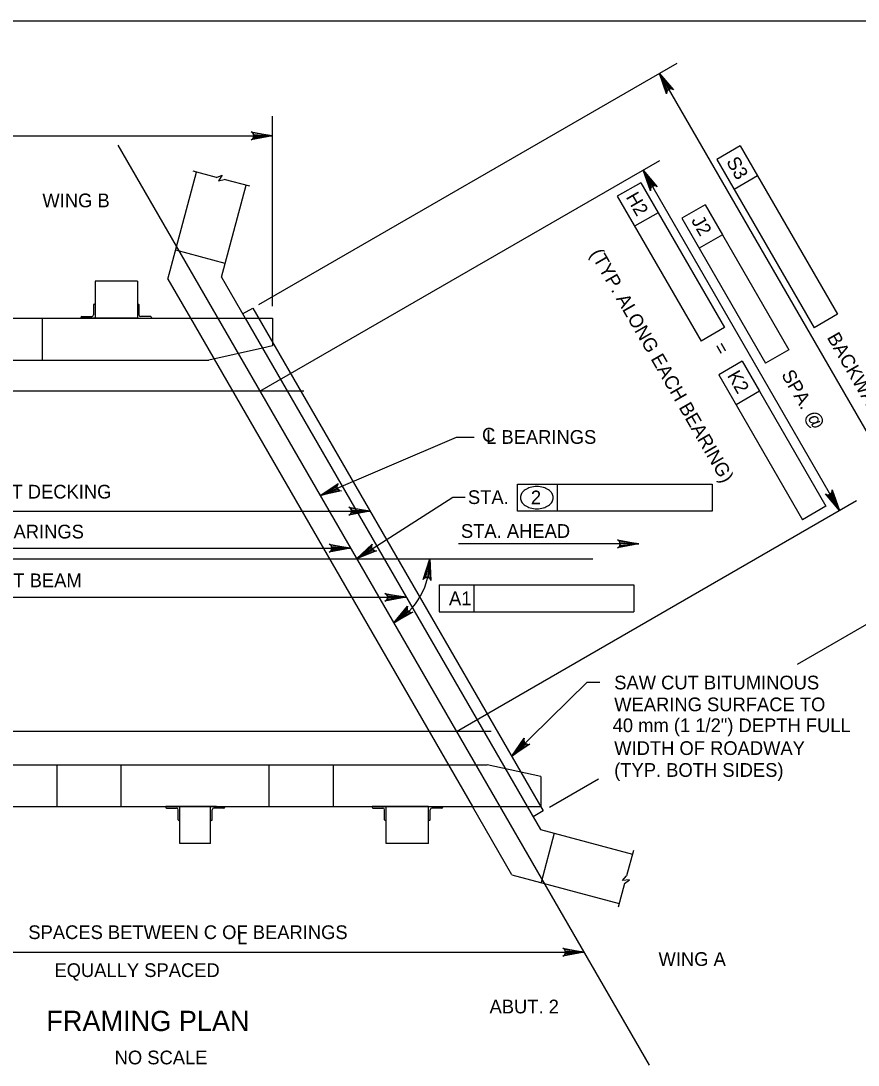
# Model space of a CAD drawing. Extents: x 638263 to 640360, y 293683 to 298655.
# Drawn here: x 638764.4 to 638947.3, y 294034.1 to 294262.5 of the extents above; entities that cross this region are included whole.
import ezdxf

# ---------------------------------------------------------------- set-up
doc = ezdxf.new("R2010")
doc.units = 0
for name, color, linetype in [('2', 7, 'Continuous'), ('3', 7, 'Continuous'), ('4', 7, 'Continuous')]:
    doc.layers.add(name, color=color, linetype=linetype)

msp = doc.modelspace()

# ---------------------------------------------------------------- linework, layer by layer
at = {"layer": '2'}
for p, q in [((638475.46, 294262.46), (639261.46, 294262.46)), ((638796.52, 294205.97), (638802.8, 294229.4)), ((638809.02, 294209.43), (638813.59, 294226.51)), ((638809.02, 294209.43), (638798.22, 294212.32)), ((638808.21, 294206.4), (638809.02, 294209.43)), ((638789.84, 294205.52), (638780.6, 294205.52)), ((638780.6, 294205.52), (638780.6, 294197.43)), ((638789.84, 294205.52), (638789.84, 294197.43)), ((638796.52, 294205.97), (638801.46, 294197.43)), ((638808.21, 294206.4), (638813.39, 294197.43)), ((638780.24, 294200.34), (638780.24, 294198.15)), ((638780.42, 294200.52), (638780.6, 294200.52)), ((638780.6, 294200.52), (638780.6, 294197.43)), ((638790.02, 294200.52), (638789.84, 294200.52)), ((638789.84, 294200.52), (638789.84, 294197.43)), ((638790.2, 294200.34), (638790.2, 294198.15)), ((638777.69, 294197.79), (638779.87, 294197.79)), ((638792.75, 294197.79), (638790.56, 294197.79)), ((638812.84, 294198.38), (638815.08, 294199.67)), ((638815.08, 294199.67), (638878.54, 294089.75)), ((638614.72, 294197.43), (638819.35, 294197.43)), ((638769.05, 294197.43), (638769.05, 294188.31)), ((638777.51, 294197.61), (638777.51, 294197.43)), ((638780.6, 294197.43), (638777.51, 294197.43)), ((638789.84, 294197.43), (638780.6, 294197.43)), ((638789.84, 294197.43), (638792.93, 294197.43)), ((638792.93, 294197.61), (638792.93, 294197.43)), ((638801.46, 294197.43), (638863.07, 294090.7)), ((638813.39, 294197.43), (638875.01, 294090.7)), ((638819.35, 294197.43), (638819.35, 294191.4)), ((638817.17, 294190.91), (638805.49, 294188.31)), ((638819.34, 294191.4), (638817.17, 294190.91)), ((638628.57, 294188.31), (638805.49, 294188.31)), ((638720.51, 294099.82), (638866.31, 294099.82)), ((638772.3, 294090.7), (638772.3, 294099.82)), ((638786.32, 294090.7), (638786.32, 294099.82)), ((638818.66, 294090.7), (638818.66, 294099.82)), ((638832.68, 294090.7), (638832.68, 294099.82)), ((638877.99, 294097.22), (638866.31, 294099.82)), ((638877.99, 294097.22), (638877.99, 294090.7)), ((638673.35, 294090.7), (638877.99, 294090.7)), ((638796.04, 294090.52), (638796.04, 294090.7)), ((638799.13, 294090.7), (638796.04, 294090.7)), ((638796.22, 294090.34), (638798.4, 294090.34)), ((638807.11, 294090.7), (638797.87, 294090.7)), ((638805.85, 294090.7), (638799.13, 294090.7)), ((638799.13, 294087.61), (638799.13, 294090.7)), ((638799.13, 294082.61), (638799.13, 294090.7)), ((638805.85, 294087.61), (638805.85, 294090.7)), ((638805.85, 294090.7), (638808.94, 294090.7)), ((638805.85, 294082.61), (638805.85, 294090.7)), ((638808.76, 294090.34), (638806.58, 294090.34)), ((638808.94, 294090.52), (638808.94, 294090.7)), ((638841.14, 294090.52), (638841.14, 294090.7)), ((638844.24, 294090.7), (638841.14, 294090.7)), ((638841.33, 294090.34), (638843.51, 294090.34)), ((638853.47, 294090.7), (638844.24, 294090.7)), ((638844.24, 294087.61), (638844.24, 294090.7)), ((638844.24, 294082.61), (638844.24, 294090.7)), ((638853.47, 294087.61), (638853.47, 294090.7)), ((638853.47, 294090.7), (638856.56, 294090.7)), ((638853.47, 294082.61), (638853.47, 294090.7)), ((638856.38, 294090.34), (638854.2, 294090.34)), ((638856.56, 294090.52), (638856.56, 294090.7)), ((638871.7, 294075.75), (638863.07, 294090.7)), ((638875.01, 294090.7), (638877.92, 294085.66)), ((638798.76, 294087.79), (638798.76, 294089.97)), ((638806.22, 294087.79), (638806.22, 294089.97)), ((638843.87, 294087.79), (638843.87, 294089.97)), ((638853.84, 294087.79), (638853.84, 294089.97)), ((638878.54, 294089.75), (638876.3, 294088.45)), ((638798.94, 294087.61), (638799.13, 294087.61)), ((638806.04, 294087.61), (638805.85, 294087.61)), ((638844.05, 294087.61), (638844.24, 294087.61)), ((638853.65, 294087.61), (638853.47, 294087.61)), ((638877.92, 294085.66), (638880.94, 294084.85)), ((638880.94, 294084.85), (638878.05, 294074.05)), ((638880.94, 294084.85), (638898.02, 294080.27)), ((638805.85, 294082.61), (638799.13, 294082.61)), ((638805.85, 294082.61), (638799.13, 294082.61)), ((638853.47, 294082.61), (638844.24, 294082.61)), ((638871.7, 294075.75), (638895.13, 294069.48))]:
    msp.add_line(p, q, dxfattribs=at)
for centre, radius, start, end in [((638780.42, 294200.34), 0.182, 90, 179.9984), ((638790.02, 294200.34), 0.182, 0.0016, 90), ((638777.69, 294197.61), 0.182, 90, 179.9984), ((638779.87, 294198.15), 0.364, 270, 359.9984), ((638790.56, 294198.15), 0.364, 180.0016, 270), ((638792.75, 294197.61), 0.182, 0.0016, 90), ((638796.22, 294090.52), 0.182, 180.0016, 270), ((638798.4, 294089.97), 0.364, 0.0016, 90), ((638806.58, 294089.97), 0.364, 90, 179.9984), ((638808.76, 294090.52), 0.182, 270, 359.9984), ((638841.33, 294090.52), 0.182, 180.0016, 270), ((638843.51, 294089.97), 0.364, 0.0016, 90), ((638854.2, 294089.97), 0.364, 90, 179.9984), ((638856.38, 294090.52), 0.182, 270, 359.9984), ((638798.94, 294087.79), 0.182, 180.0016, 270), ((638806.04, 294087.79), 0.182, 270, 359.9984), ((638844.05, 294087.79), 0.182, 180.0016, 270), ((638853.65, 294087.79), 0.182, 270, 359.9984)]:
    msp.add_arc(centre, radius, start, end, dxfattribs=at)
at = {"layer": '3'}
for p, q in [((638785.58, 294235.25), (638901.7, 294034.14)), ((638807.16, 294228.23), (638802.04, 294229.6)), ((638807.16, 294228.23), (638808.37, 294228.75)), ((638808.37, 294228.75), (638807.54, 294227.5)), ((638807.54, 294227.5), (638808.83, 294227.79)), ((638814.43, 294226.29), (638808.83, 294227.79)), ((638898.25, 294081.1), (638896.75, 294075.5)), ((638895.86, 294074.53), (638896.75, 294075.5)), ((638897.35, 294074.62), (638895.86, 294074.53)), ((638896.3, 294073.84), (638897.35, 294074.62)), ((638896.3, 294073.84), (638894.93, 294068.71))]:
    msp.add_line(p, q, dxfattribs=at)
at = {"layer": '4'}
for p, q in [((638816.41, 294200.44), (638907.77, 294253.19)), ((638903.93, 294250.97), (638967.4, 294141.05)), ((638819.35, 294200.07), (638819.35, 294241.6)), ((638614.72, 294237.34), (638819.35, 294237.34)), ((638921.59, 294235.12), (638916.48, 294232.17)), ((638921.59, 294235.12), (638925.37, 294228.57)), ((638816.64, 294181.46), (638904.03, 294231.91)), ((638916.48, 294232.17), (638937.74, 294195.34)), ((638943.26, 294155.42), (638900.37, 294229.79)), ((638925.37, 294228.57), (638920.26, 294225.62)), ((638925.37, 294228.57), (638942.85, 294198.3)), ((638899.84, 294227.07), (638894.72, 294224.11)), ((638899.84, 294227.07), (638903.62, 294220.52)), ((638894.72, 294224.11), (638913.01, 294192.44)), ((638903.62, 294220.52), (638898.5, 294217.57)), ((638903.62, 294220.52), (638918.12, 294195.39)), ((638913.94, 294222.24), (638908.82, 294219.29)), ((638913.94, 294222.24), (638917.72, 294215.69)), ((638908.82, 294219.29), (638927.11, 294187.61)), ((638917.72, 294215.69), (638912.6, 294212.74)), ((638917.72, 294215.69), (638932.23, 294190.56)), ((638942.85, 294198.3), (638937.74, 294195.34)), ((638918.12, 294195.39), (638913.01, 294192.44)), ((638932.23, 294190.56), (638927.11, 294187.61)), ((638921.99, 294188.02), (638916.88, 294185.07)), ((638921.99, 294188.02), (638925.77, 294181.47)), ((638916.88, 294185.07), (638935.17, 294153.39)), ((638826.19, 294181.46), (638525.77, 294181.46)), ((638925.77, 294181.47), (638920.66, 294178.52)), ((638925.77, 294181.47), (638940.28, 294156.35)), ((638829.8, 294158.66), (638859.55, 294171.47)), ((638859.55, 294171.47), (638863.41, 294171.47)), ((638872.9, 294155.27), (638872.9, 294161.18)), ((638872.9, 294161.18), (638881.65, 294161.18)), ((638881.65, 294155.27), (638881.65, 294161.18)), ((638881.65, 294161.18), (638915.42, 294161.18)), ((638915.42, 294161.18), (638915.42, 294155.27)), ((638837.74, 294144.81), (638858.76, 294158.33)), ((638858.76, 294158.33), (638861.5, 294158.33)), ((638859.57, 294107.1), (638946.96, 294157.56)), ((638639.07, 294155.25), (638840.72, 294155.25)), ((638915.42, 294155.27), (638872.9, 294155.27)), ((638940.28, 294156.35), (638935.17, 294153.39)), ((638899.41, 294148.08), (638860.04, 294148.08)), ((638652.67, 294147.2), (638836.42, 294147.2)), ((638587.79, 294144.82), (638889.34, 294144.82)), ((638934.12, 294121.83), (638971.23, 294143.26)), ((638855.82, 294139.15), (638863.38, 294139.15)), ((638855.82, 294139.15), (638855.82, 294133.25)), ((638863.38, 294139.15), (638863.38, 294133.25)), ((638863.38, 294139.15), (638898.34, 294139.15)), ((638898.34, 294139.15), (638898.34, 294133.25)), ((638652.93, 294136.42), (638848.61, 294136.42)), ((638855.82, 294133.25), (638898.34, 294133.25)), ((638871.64, 294101.7), (638888.1, 294117.89)), ((638888.1, 294117.89), (638890.93, 294117.89)), ((638867.19, 294107.1), (638525.47, 294107.1)), ((638879.87, 294090.52), (638890.61, 294096.71)), ((638703.7, 294058.82), (638887.45, 294058.82))]:
    msp.add_line(p, q, dxfattribs=at)
for points in [[(638905.83, 294248.66), (638904.98, 294248.17), (638903.93, 294250.97)], [(638901.37, 294227.1), (638902.19, 294227.57), (638900.37, 294229.79)], [(638941.44, 294157.64), (638942.25, 294158.11), (638943.26, 294155.42)], [(638874.34, 294103.7), (638873.68, 294104.37), (638871.99, 294102.05)]]:
    msp.add_lwpolyline(points, close=True, dxfattribs=at)
for points in [[(638903.93, 294250.97), (638907.02, 294247.37), (638906.62, 294247.56), (638906.26, 294247.57), (638905.96, 294247.46), (638905.72, 294247.25), (638905.54, 294246.94), (638905.5, 294246.5), (638903.93, 294250.97), (638905.54, 294246.94), (638905.72, 294247.25), (638903.93, 294250.97), (638905.96, 294247.46), (638906.26, 294247.57), (638903.93, 294250.97), (638906.62, 294247.56)], [(638819.35, 294237.34), (638814.69, 294236.46), (638815.05, 294236.71), (638815.24, 294237.02), (638815.29, 294237.34), (638815.24, 294237.65), (638815.05, 294237.96), (638814.69, 294238.21), (638819.35, 294237.34), (638815.05, 294237.96), (638815.24, 294237.65), (638819.35, 294237.34), (638815.29, 294237.34), (638815.24, 294237.02), (638819.35, 294237.34), (638815.05, 294236.71)], [(638900.37, 294229.79), (638903.45, 294226.19), (638903.05, 294226.38), (638902.69, 294226.38), (638902.39, 294226.27), (638902.15, 294226.07), (638901.97, 294225.76), (638901.94, 294225.32), (638900.37, 294229.79), (638901.97, 294225.76), (638902.15, 294226.07), (638900.37, 294229.79), (638902.39, 294226.27), (638902.69, 294226.38), (638900.37, 294229.79), (638903.05, 294226.38)], [(638829.8, 294158.66), (638833.74, 294161.31), (638833.51, 294160.94), (638833.46, 294160.58), (638833.53, 294160.27), (638833.71, 294160), (638834, 294159.79), (638834.43, 294159.7), (638829.8, 294158.66), (638834, 294159.79), (638833.71, 294160), (638829.8, 294158.66), (638833.53, 294160.27), (638833.46, 294160.58), (638829.8, 294158.66), (638833.51, 294160.94)], [(638943.26, 294155.42), (638940.18, 294159.02), (638940.57, 294158.83), (638940.93, 294158.83), (638941.23, 294158.94), (638941.48, 294159.14), (638941.65, 294159.46), (638941.69, 294159.89), (638943.26, 294155.42), (638941.65, 294159.46), (638941.48, 294159.14), (638943.26, 294155.42), (638941.23, 294158.94), (638940.93, 294158.83), (638943.26, 294155.42), (638940.57, 294158.83)], [(638840.72, 294155.25), (638836.06, 294154.38), (638836.42, 294154.63), (638836.6, 294154.94), (638836.66, 294155.25), (638836.6, 294155.57), (638836.42, 294155.88), (638836.06, 294156.13), (638840.72, 294155.25), (638836.42, 294155.88), (638836.6, 294155.57), (638840.72, 294155.25), (638836.66, 294155.25), (638836.6, 294154.94), (638840.72, 294155.25), (638836.42, 294154.63)], [(638836.42, 294147.2), (638831.76, 294146.33), (638832.12, 294146.57), (638832.3, 294146.89), (638832.36, 294147.2), (638832.3, 294147.51), (638832.12, 294147.82), (638831.76, 294148.07), (638836.42, 294147.2), (638832.12, 294147.82), (638832.3, 294147.51), (638836.42, 294147.2), (638832.36, 294147.2), (638832.3, 294146.89), (638836.42, 294147.2), (638832.12, 294146.57)], [(638837.74, 294144.81), (638841.18, 294148.06), (638841.02, 294147.66), (638841.03, 294147.3), (638841.15, 294147), (638841.37, 294146.77), (638841.69, 294146.61), (638842.13, 294146.59), (638837.74, 294144.81), (638841.69, 294146.61), (638841.37, 294146.77), (638837.74, 294144.81), (638841.15, 294147), (638841.03, 294147.3), (638837.74, 294144.81), (638841.02, 294147.66)], [(638899.41, 294148.08), (638894.75, 294147.21), (638895.11, 294147.46), (638895.3, 294147.77), (638895.35, 294148.08), (638895.3, 294148.4), (638895.11, 294148.71), (638894.75, 294148.96), (638899.41, 294148.08), (638895.11, 294148.71), (638895.3, 294148.4), (638899.41, 294148.08), (638895.35, 294148.08), (638895.3, 294147.77), (638899.41, 294148.08), (638895.11, 294147.46)], [(638853.75, 294144.82), (638854, 294140.09), (638853.81, 294140.47), (638853.52, 294140.7), (638853.22, 294140.79), (638852.9, 294140.78), (638852.57, 294140.64), (638852.27, 294140.32), (638853.75, 294144.82), (638852.57, 294140.64), (638852.9, 294140.78), (638853.75, 294144.82), (638853.22, 294140.79), (638853.52, 294140.7), (638853.75, 294144.82), (638853.81, 294140.47)], [(638848.61, 294136.42), (638843.95, 294135.55), (638844.31, 294135.8), (638844.5, 294136.11), (638844.55, 294136.42), (638844.5, 294136.73), (638844.31, 294137.05), (638843.95, 294137.29), (638848.61, 294136.42), (638844.31, 294137.05), (638844.5, 294136.73), (638848.61, 294136.42), (638844.55, 294136.42), (638844.5, 294136.11), (638848.61, 294136.42), (638844.31, 294135.8)], [(638845.88, 294130.82), (638848.88, 294134.49), (638848.77, 294134.07), (638848.83, 294133.71), (638848.99, 294133.44), (638849.23, 294133.23), (638849.57, 294133.11), (638850.01, 294133.15), (638845.88, 294130.82), (638849.57, 294133.11), (638849.23, 294133.23), (638845.88, 294130.82), (638848.99, 294133.44), (638848.83, 294133.71), (638845.88, 294130.82), (638848.77, 294134.07)], [(638871.64, 294101.7), (638874.35, 294105.59), (638874.27, 294105.16), (638874.35, 294104.81), (638874.54, 294104.55), (638874.79, 294104.37), (638875.14, 294104.27), (638875.58, 294104.35), (638871.64, 294101.7), (638875.14, 294104.27), (638874.79, 294104.37), (638871.64, 294101.7), (638874.54, 294104.55), (638874.35, 294104.81), (638871.64, 294101.7), (638874.27, 294105.16)], [(638887.45, 294058.82), (638882.79, 294057.95), (638883.15, 294058.19), (638883.33, 294058.51), (638883.39, 294058.82), (638883.33, 294059.13), (638883.15, 294059.44), (638882.79, 294059.69), (638887.45, 294058.82), (638883.15, 294059.44), (638883.33, 294059.13), (638887.45, 294058.82), (638883.39, 294058.82), (638883.33, 294058.51), (638887.45, 294058.82), (638883.15, 294058.19)]]:
    msp.add_lwpolyline(points, dxfattribs=at)
for centre, radius, start, end in [((638875.23, 294158.21), 1.68, 148.5507, 180), ((638876.14, 294157.65), 2.75, 124.109, 148.5507), ((638876.74, 294156.77), 3.82, 105.6708, 124.109), ((638877.13, 294155.37), 5.27, 90, 105.6708), ((638877.13, 294155.37), 5.27, 74.3292, 90), ((638877.53, 294156.77), 3.82, 55.891, 74.3292), ((638878.13, 294157.65), 2.75, 31.4493, 55.891), ((638879.04, 294158.21), 1.68, 0, 31.4493), ((638875.23, 294158.21), 1.68, 180, 211.4493), ((638876.14, 294158.77), 2.75, 211.4493, 235.891), ((638878.13, 294158.77), 2.75, 304.109, 328.5507), ((638879.04, 294158.21), 1.68, 328.5507, 0), ((638876.74, 294159.66), 3.82, 235.891, 254.3292), ((638877.13, 294161.06), 5.27, 254.3292, 270), ((638877.13, 294161.06), 5.27, 270, 285.6708), ((638877.53, 294159.66), 3.82, 285.6708, 304.109), ((638837.99, 294144.48), 15.77, 299.9997, 1.2352)]:
    msp.add_arc(centre, radius, start, end, dxfattribs=at)

# ---------------------------------------------------------------- texts
for s, height, rotation, p in [('S3', 3, 299.9382, (638918.43, 294231.7)), ('H2', 3, 299.9382, (638896.5, 294223.94)), ('J2', 3, 299.9382, (638910.78, 294218.81)), ('(TYP. ALONG EACH BEARING)', 3, 299.9745, (638888.68, 294211.57)), ('BACKWALL LENGTH', 3, 299.9745, (638940.44, 294193.25)), ('= ', 2.953, 299.9745, (638915.63, 294191.15)), ('K2', 3, 299.9382, (638918.64, 294184.93)), ('SPA. @', 3, 299.9745, (638930.47, 294185.12)), ('A1', 3, 359.9382, (638857.94, 294134.7))]:
    msp.add_text(s, height=height, rotation=rotation, dxfattribs=at).set_placement(p)
for s, height, p in [('WING B', 3, (638769.09, 294221.7)), ('C', 3.02, (638865.15, 294170.45)), ('L BEARINGS', 3, (638866.05, 294169.98)), ('OUT TO OUT DECKING', 3, (638740.05, 294158.02)), ('STA.', 3, (638862.08, 294156.82)), ('2', 3, (638875.83, 294156.76)), ('C/C BEARINGS', 3, (638749.41, 294149.29)), ('STA. AHEAD', 3, (638860.55, 294149.42)), ('OUT TO OUT BEAM', 3, (638740.46, 294138.63)), ('SAW CUT BITUMINOUS', 3, (638894.04, 294116.29)), ('WEARING SURFACE TO ', 3, (638894.04, 294111.51)), ('40 mm (1 1/2") DEPTH FULL', 3, (638893.7, 294106.94)), ('WIDTH OF ROADWAY', 3, (638894.04, 294101.95)), ('(TYP. BOTH SIDES)', 3, (638894.04, 294097.17)), ('SPACES BETWEEN C OF BEARINGS', 3, (638766.02, 294061.7)), ('L', 3, (638811.63, 294060.57)), ('WING A', 3, (638903.72, 294055.83)), ('EQUALLY SPACED', 3, (638771.72, 294053.4)), ('ABUT. 2', 3, (638866.8, 294045.45)), ('FRAMING PLAN', 4.4292, (638769.94, 294041.59)), ('NO SCALE', 3, (638784.88, 294034.31))]:
    msp.add_text(s, height=height, dxfattribs=at).set_placement(p)

doc.saveas('drawing.dxf')
